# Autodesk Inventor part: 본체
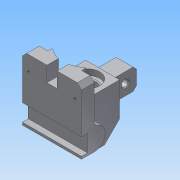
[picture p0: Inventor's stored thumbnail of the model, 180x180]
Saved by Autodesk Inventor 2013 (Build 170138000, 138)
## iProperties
Created: 2016-11
Part Number: 본체
Material: 알루미늄 6061
Document SubType Name: Modeling
Designer: Administrator
Density: 2.71 g/cm^3
Mass: 462.697 g
Surface Area: 317.767 cm^2
Volume: 170.737 cm^3
Author: Administrator
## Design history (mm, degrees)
sketch "스케치1"
  geometry: L1 (-20, 18)-(0, 18); L2 (0, 18)-(0, -30); L3 (0, -30)-(-20, -30); L4 (-20, -30)-(-20, 18); 2 further points
  constraints: 8 end point, 2 parallel, 1 coincident, 1 horizontal, 1 perpendicular, 1 vertical alignment
  dimensions: "d3" = 20 distance of L1.start L1.end; "d5" = 30 distance from line of point (0, 0) L3; "d7" = 48 distance of L3.end L1.start
extrude "돌출1" new body sketch "스케치1" distance "d8" = 28; taper "d9" = 0 deg
sketch "스케치2"
  geometry: L1 (20, 18)-(0, 18) reference; L2 (0, 18)-(0, -30) reference; L3 (0, -30)-(20, -30) reference; L4 (20, -30)-(20, 18) reference; 1 further point
extrude "돌출2" join sketch "스케치2" distance "d10" = 30; taper "d11" = 0 deg
sketch "스케치3"
  geometry: 2 further points
  constraints: 1 coincident
hole "구멍1" sketch "스케치3" at (0, 0) diameter "d12" = 20; stored, may be unused: countersink angle "d16" = 90 deg, drill point angle "d18" = 118 deg; dims "d13" = 6, "d14" = 29, "d15" = 7, "d17" = 8
sketch "스케치4"
  geometry: L1 (-58, 48)-(0, 48) reference; L2 (-58, 0)-(-58, 48) reference; L3 (-58, 30)-(-40, 48); 1 further point
  constraints: 2 end point, 2 point on line
  dimensions: "d19" = 45 deg angle of L2 L3; "d20" = 18 distance from line of L3.end L2
extrude "돌출3" cut sketch "스케치4" distance "d21" = 30; taper "d22" = 0 deg
sketch "스케치6"
  geometry: L1 (20, 0)-(0, 0) reference; L2 (10, 30)-(20, 30); L3 (20, 30)-(20, 5); L4 (20, 5)-(10, 5); L5 (10, 5)-(10, 30); 2 further points
  constraints: 8 end point, 2 parallel, 1 horizontal, 1 perpendicular, 1 vertical alignment
  dimensions: "d27" = 25 distance of L4.end L2.start; "d29" = 10 distance of L2.start L2.end; "d30" = 5 distance between parallel lines of L4 L1
extrude "돌출4" join sketch "스케치6" distance "d31" = 30; taper "d32" = 0 deg
sketch "스케치7"
  geometry: L1 (0, 30)-(25, 30) reference; L2 (0, 0)-(0, 30) reference; 2 further points
  dimensions: "d33" = 12.5 distance from line of point (12.5, 17) L2; "d34" = 13 distance from line of point (12.5, 17) L1
hole "구멍2" sketch "스케치7" at (12.5, 17) diameter "d35" = 8; stored, may be unused: countersink angle "d39" = 90 deg, drill point angle "d41" = 118 deg; dims "d36" = 6, "d37" = 29, "d38" = 7, "d40" = 8
chamfer "모따기1" distance "d42" = 4; stored, may be unused: second distance "d43" = 2, angle "d44" = 45 deg
sketch "스케치8"
  geometry: L1 (-58, 4)-(-58, 30) reference; L2 (-18, 3)-(32, 3); L3 (32, 3)-(32, -12); L4 (-44, -12)-(-44, 3); L5 (-41, -12)-(-41, -5); L6 (-41, -5)-(-21, -5); L7 (-21, -5)-(-21, -12); L8 (32, -12)-(-21, -12); L9 (-41, -12)-(-44, -12); C1 r 4 at (-17.5, 65) reference; A1 r 13 centre (-31, 3) between (-18, 3) and (-44, 3); 1 further point
  constraints: 16 end point, 5 parallel, 4 perpendicular, 2 point on circle, 1 centre point, 1 horizontal, 1 horizontal alignment, 1 tangent
  dimensions: "d45" = 26 diameter of A1; "d46" = 15 distance of L2.end L3.end; "d48" = 63 distance from line of A1.centre L3; "d49" = 90 distance between parallel lines of L3 L1; "d50" = 7 distance of L5.start L5.end; "d51" = 3 distance of L5.start L4.start; "d52" = 20 distance of L5.end L6.end; "d53" = 77 distance from line of L8 C1.centre
extrude "돌출5" join sketch "스케치8" distance "d54" = 15; taper "d55" = 0 deg; dims "d56" = 20, "d57" = 0
fillet "모깎기1" dims "d58" = 5, "d59" = 3
chamfer "모따기2" distance "d60" = 1; stored, may be unused: second distance "d61" = 2, angle "d62" = 45 deg
sketch "스케치9"
  geometry: L1 (35, 0)-(0, 0) reference; L2 (35, 32)-(35, 0) reference; 3 further points
  dimensions: "d63" = 18 distance from line of point (7.5, 18) L1; "d64" = 27.5 distance from line of L2 point (7.5, 18)
hole "구멍3" sketch "스케치9" at (7.5, 18) diameter "d65" = 3.242; stored, may be unused: countersink angle "d69" = 90 deg, drill point angle "d71" = 118 deg; dims "d66" = 6, "d67" = 29, "d68" = 7, "d70" = 8
chamfer "모따기3" distance "d72" = 5; stored, may be unused: second distance "d73" = 2, angle "d74" = 45 deg
sketch "스케치5"
  geometry: L1 (0, 48)-(0, 0) reference; L2 (-40, 48)-(0, 48) reference; 2 further points
  constraints: 1 other
  dimensions: "d23" = 25 distance from line of point (-25, 30) L1; "d24" = 18 distance from line of point (-25, 30) L2
feature "엠보싱1" sketch "스케치5" dims "d3" = 20, "d5" = 30, "d7" = 48, "d25" = 0.5, "d26" = 0
sketch "스케치10"
  geometry: L1 (20, 18)-(20, -27) reference; L2 (-20, 18)-(-20, -27) reference; L3 (-20, -22)-(20, -22); L4 (20, -22)-(20, -27); L5 (20, -27)-(-20, -27); L6 (-20, -27)-(-20, -22); 1 further point
  constraints: 8 end point, 2 parallel, 2 point on line, 1 horizontal, 1 horizontal alignment, 1 midpoint, 1 perpendicular, 1 vertical alignment
  dimensions: "d75" = 5 distance of L3.end L4.end
extrude "돌출6" join sketch "스케치10" stored distance "d77" = 10; taper "d78" = 0 deg
sketch "스케치11"
  geometry: L1 (0, -15)-(60, -15) reference; L2 (10, 5)-(50, 5) reference; L3 (10, 0)-(0, 0) reference; L4 (24, -15)-(24, -1.373); L5 (36, -15)-(36, -1.373); A1 r 29 centre (30, 27) between (11.106, 5) and (24, -1.373); A2 r 29 centre (30, 27) between (48.894, 5) and (11.106, 5); A3 r 29 centre (30, 27) between (24, -1.373) and (36, -1.373); A4 r 29 centre (30, 27) between (36, -1.373) and (48.894, 5); 1 further point
  constraints: 9 point on circle, 4 centre point, 4 end point, 4 point on line, 1 coincident, 1 parallel, 1 perpendicular
  dimensions: "d79" = 29 radius of A1; "d80" = 12 distance between parallel lines of L5 L4; "d81" = 6 distance from line of point (30, 27) L5
extrude "돌출7" cut sketch "스케치11" distance "d82" = 18; taper "d83" = 0 deg
fillet "모깎기2" dims "d84" = 3
node "솔리드1"
mirror "대칭1"
